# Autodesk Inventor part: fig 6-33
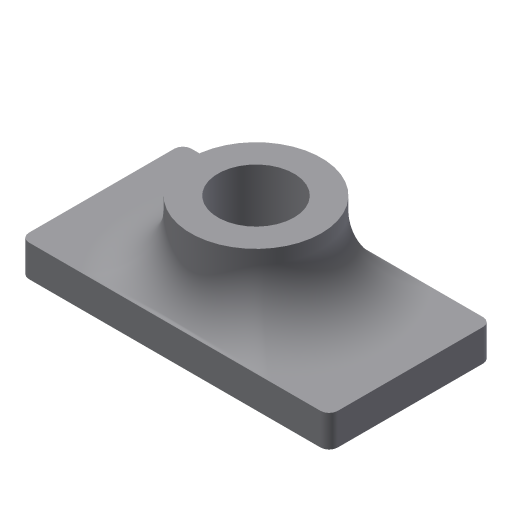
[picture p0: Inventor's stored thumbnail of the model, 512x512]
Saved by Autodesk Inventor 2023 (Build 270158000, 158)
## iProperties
Created: 2004-05
Part Number: fig 6-33
Document SubType Name: Modeling
Designer: CADCIM Technologies
Manufacturer: Standard
Standards Organization: Custom
Density: 1 g/cm^3
Material: Generic
Appearance: Default
Author: CADCIM Technologies
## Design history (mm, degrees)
sketch "Sketch1"
  geometry: L1 (-39.276, -18.692)-(33.721, -18.692); L2 (33.721, -18.692)-(33.721, 19.728); L3 (33.721, 19.728)-(-39.276, 19.728); L4 (-39.276, 19.728)-(-39.276, -18.692)
  constraints: 8 end point, 2 parallel, 1 horizontal, 1 perpendicular
extrude "Extrusion1" new body sketch "Sketch1" distance "d0" = 7.5; taper "d1" = 0 deg
fillet "Fillet1" dims "d2" = 2
sketch "Sketch2"
  geometry: C1 r 15.456 at (-2.778, 0.518)
  constraints: 1 centre point
extrude "Extrusion2" join sketch "Sketch2" distance "d3" = 17.25; taper "d4" = 0 deg
hole "Hole1" diameter "d8" = 18; stored, may be unused: countersink angle "d12" = 90 deg, drill point angle "d14" = 118 deg; dims "d6" = 10, "d7" = 10, "d9" = 6, "d10" = 4, "d11" = 2, "d13" = 8
fillet "Fillet2" dims "d5" = 14
body "Solid1"
